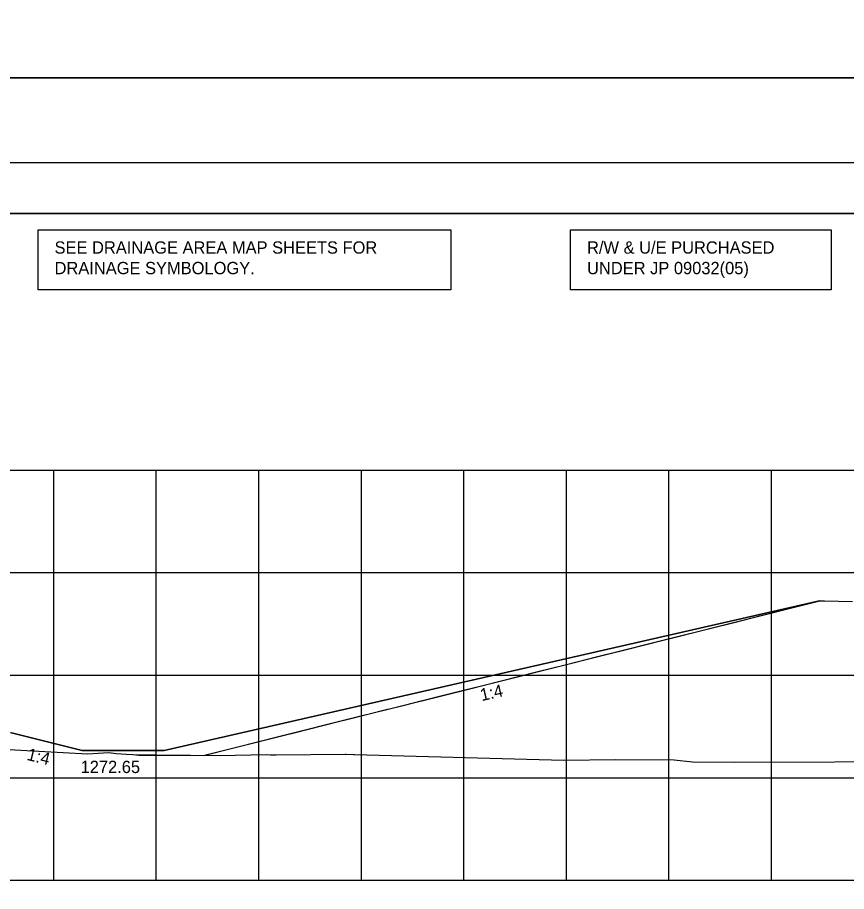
# Model space of a CAD drawing. Extents: x 2148105 to 2149976, y 144169 to 149705.
# Drawn here: x 2148429.8 to 2148510.6, y 148905.8 to 148991 of the extents above; entities that cross this region are included whole.
import ezdxf

# ---------------------------------------------------------------- set-up
doc = ezdxf.new("R2010")
doc.units = 0
for name, color, linetype in [('INR_Tracking', 7, 'Continuous'), ('PH1a-2-RampC', 7, 'Continuous'), ('PH1a-PR-DividingStrip', 7, 'Continuous'), ('PH1a-PR-ServRd', 7, 'Continuous'), ('PR-ApproachSlab', 7, 'Continuous'), ('PR-SHLDR-RMP-H', 7, 'Continuous'), ('PR_Align_Ramp_E', 7, 'Continuous'), ('PR_Align_Ramp_J', 7, 'Continuous'), ('PR_Storm_Conc_Box_PH1B', 7, 'Continuous'), ('PR_Storm_Conc_Pipe_PH1B', 7, 'Continuous'), ('PR_Storm_Inlet_CICI_PH1B', 7, 'Continuous'), ('PR_Storm_MH', 7, 'Continuous'), ('PR_Storm_Standard_Median_Drain_PH1B', 7, 'Continuous'), ('TopCut', 7, 'Continuous')]:
    doc.layers.add(name, color=color, linetype=linetype)

msp = doc.modelspace()

# ---------------------------------------------------------------- linework, layer by layer
at = {"layer": 'INR_Tracking'}
msp.add_lwpolyline([(2148398.322, 148922.853), (2148413.317, 148922.088), (2148413.322, 148922.088), (2148415.322, 148921.986), (2148423.318, 148921.578), (2148423.322, 148921.578), (2148424.545, 148921.515), (2148425.312, 148921.476), (2148429.183, 148921.278), (2148429.192, 148921.277), (2148429.209, 148921.273), (2148436.073, 148919.558), (2148436.079, 148919.558), (2148441.355, 148919.558), (2148444.073, 148919.558), (2148508.026, 148934.14), (2148508.041, 148934.143)], dxfattribs=at)
at = {"layer": 'PH1a-PR-ServRd'}
msp.add_lwpolyline([(2148570.822, 148761.906), (2148255.822, 148761.906), (2148255.822, 148971.906), (2148570.822, 148971.906)], close=True, dxfattribs=at)
at = {"layer": 'PR-ApproachSlab'}
msp.add_lwpolyline([(2148447.937, 148919.075), (2148448.071, 148919.108), (2148448.084, 148919.111), (2148448.296, 148919.164), (2148456.098, 148921.12), (2148456.767, 148921.288), (2148461.107, 148922.375), (2148462.037, 148922.609), (2148465.887, 148923.573), (2148466.057, 148923.616), (2148467.536, 148923.987), (2148469.293, 148924.427), (2148471.085, 148924.877), (2148473.272, 148925.425), (2148475.042, 148925.869), (2148480.549, 148927.248), (2148483.208, 148927.915), (2148486.364, 148928.707), (2148488.324, 148929.198), (2148491.936, 148930.104), (2148493.39, 148930.469), (2148497.446, 148931.486), (2148499.701, 148932.052), (2148502.335, 148932.712), (2148508.04, 148934.143), (2148508.18, 148934.141), (2148508.515, 148934.135), (2148511.226, 148934.087)], dxfattribs=at)
at = {"layer": 'PR-SHLDR-RMP-H'}
msp.add_lwpolyline([(2148447.937, 148919.075), (2148453.719, 148920.525), (2148454.73, 148920.778), (2148463.154, 148922.89), (2148465.803, 148923.554), (2148472.458, 148925.222), (2148476.717, 148926.29), (2148481.638, 148927.524), (2148487.47, 148928.986), (2148489.172, 148929.412), (2148492.637, 148930.281), (2148493.974, 148930.617), (2148498.069, 148931.643), (2148499.626, 148932.033), (2148508.04, 148934.143), (2148508.18, 148934.141), (2148508.515, 148934.135), (2148511.226, 148934.087)], dxfattribs=at)
at = {"layer": 'PR_Align_Ramp_E'}
for points in [[(2148219.947, 149225.156), (2148579.947, 149225.156), (2148579.947, 148985.156), (2148219.947, 148985.156)], [(2148219.947, 148985.156), (2148579.947, 148985.156), (2148579.947, 148745.156), (2148219.947, 148745.156)]]:
    msp.add_lwpolyline(points, close=True, dxfattribs=at)
at = {"layer": 'PR_Align_Ramp_J'}
msp.add_lwpolyline([(2148236.322, 148976.906), (2148576.322, 148976.906), (2148576.322, 148756.906), (2148236.322, 148756.906)], close=True, dxfattribs=at)
at = {"layer": 'PR_Storm_Conc_Box_PH1B'}
for p, q in [((2148263.322, 148946.906), (2148563.322, 148946.906)), ((2148433.322, 148906.906), (2148433.322, 148946.906)), ((2148443.322, 148906.906), (2148443.322, 148946.906)), ((2148453.322, 148906.906), (2148453.322, 148946.906)), ((2148463.322, 148906.906), (2148463.322, 148946.906)), ((2148473.322, 148906.906), (2148473.322, 148946.906)), ((2148483.322, 148906.906), (2148483.322, 148946.906)), ((2148493.322, 148906.906), (2148493.322, 148946.906)), ((2148503.322, 148906.906), (2148503.322, 148946.906)), ((2148263.322, 148936.906), (2148563.322, 148936.906)), ((2148263.322, 148926.906), (2148563.322, 148926.906)), ((2148263.322, 148916.906), (2148563.322, 148916.906)), ((2148263.322, 148906.906), (2148563.322, 148906.906))]:
    msp.add_line(p, q, dxfattribs=at)
at = {"layer": 'PR_Storm_Conc_Pipe_PH1B'}
msp.add_lwpolyline([(2148255.822, 148761.906), (2148570.822, 148761.906), (2148570.822, 148971.906), (2148255.822, 148971.906)], close=True, dxfattribs=at)
msp.add_lwpolyline([(2148255.822, 148761.906), (2148570.822, 148761.906), (2148570.822, 148971.906), (2148255.822, 148971.906)], close=True, dxfattribs=at)
at = {"layer": 'PR_Storm_Inlet_CICI_PH1B'}
msp.add_lwpolyline([(2148428.942, 148919.663), (2148431.85, 148919.508), (2148436.618, 148919.233), (2148438.679, 148919.367), (2148439.419, 148919.263), (2148440.396, 148919.208), (2148441.034, 148919.174), (2148441.631, 148919.095), (2148444.277, 148919.118), (2148449.501, 148919.057), (2148454.031, 148919.154), (2148454.448, 148919.15), (2148455.01, 148919.145), (2148461.742, 148919.199), (2148461.851, 148919.21), (2148462.546, 148919.182), (2148462.665, 148919.17), (2148483.086, 148918.625), (2148488.113, 148918.69), (2148493.843, 148918.643), (2148495.629, 148918.457), (2148499.674, 148918.421), (2148509.518, 148918.446), (2148513.368, 148918.479)], dxfattribs=at)
at = {"layer": 'PR_Storm_MH'}
for points in [[(2148431.781, 148970.339), (2148472.066, 148970.339), (2148472.066, 148964.468), (2148431.781, 148964.468)], [(2148483.725, 148970.339), (2148509.146, 148970.339), (2148509.146, 148964.468), (2148483.725, 148964.468)]]:
    msp.add_lwpolyline(points, close=True, dxfattribs=at)
at = {"layer": 'PR_Storm_Standard_Median_Drain_PH1B'}
msp.add_line((2148263.322, 148906.906), (2148563.322, 148906.906), dxfattribs=at)
at = {"layer": 'TopCut'}
msp.add_lwpolyline([(2148428.942, 148919.663), (2148431.85, 148919.508), (2148436.618, 148919.233), (2148438.679, 148919.367), (2148439.419, 148919.263), (2148440.396, 148919.208), (2148441.034, 148919.174), (2148445.452, 148919.105), (2148446.649, 148919.09), (2148447.937, 148919.075), (2148453.719, 148920.525), (2148454.73, 148920.778), (2148463.154, 148922.89), (2148465.803, 148923.554), (2148472.458, 148925.222), (2148476.717, 148926.29), (2148481.638, 148927.524), (2148487.47, 148928.986), (2148489.172, 148929.412), (2148492.637, 148930.281), (2148493.974, 148930.617), (2148498.069, 148931.643), (2148499.626, 148932.033), (2148508.037, 148934.142), (2148508.026, 148934.14), (2148444.073, 148919.558), (2148441.355, 148919.558), (2148436.079, 148919.558), (2148436.073, 148919.558), (2148429.209, 148921.273)], dxfattribs=at)

# ---------------------------------------------------------------- texts
at = {"layer": 'PH1a-2-RampC'}
msp.add_text('1272.65', height=1.2, dxfattribs=at).set_placement((2148435.935, 148917.358))
at = {"layer": 'PH1a-PR-DividingStrip'}
for rotation, p in [(12.84414, (2148475.057, 148924.366)), (345.97199, (2148430.618, 148918.653))]:
    msp.add_text('1:4', height=1.2, rotation=rotation, dxfattribs=at).set_placement(p)
at = {"layer": 'PR_Storm_MH'}
for s, p in [('SEE DRAINAGE AREA MAP SHEETS FOR', (2148433.395, 148968.002)), ('R/W & U/E PURCHASED', (2148485.338, 148968.002)), ('DRAINAGE SYMBOLOGY.', (2148433.395, 148965.998)), ('UNDER JP 09032(05)', (2148485.338, 148965.998))]:
    msp.add_text(s, height=1.2, dxfattribs=at).set_placement(p)

doc.saveas('drawing.dxf')
